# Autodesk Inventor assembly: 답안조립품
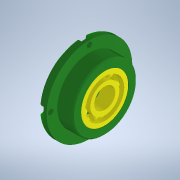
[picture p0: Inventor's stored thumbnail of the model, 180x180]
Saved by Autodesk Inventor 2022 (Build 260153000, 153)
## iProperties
Created: 2023-04
Part Number: 답안조립품
Document SubType Name: Assembly
Designer: Admin
Author: Admin
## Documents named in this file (5)
- C:\Users\Admin\Desktop\730411V1001\답안조립품.iam
- C:\Users\Admin\Desktop\730411V1001\본체.ipt
- C:\Users\Admin\Desktop\730411V1001\커버.ipt
- C:\Users\Admin\Desktop\730411V1001\베어링 6203.ipt
- C:\Users\Admin\Desktop\730411V1001\오일실 17 x 32 x 8.ipt
